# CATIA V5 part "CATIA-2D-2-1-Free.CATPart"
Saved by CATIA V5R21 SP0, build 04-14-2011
Part number: CATIA-2D-2-1-Free
Bounding box of the stored display mesh (mm): x -1249.99 to 1249.99, y 0 to 0, z -1200.054 to 1124.626
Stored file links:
  C:\Users\Rasoul Mohammadi\Desktop\CATIA-Free\2D\CATIA-2D-2-1-Free.CATPart
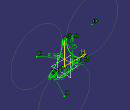
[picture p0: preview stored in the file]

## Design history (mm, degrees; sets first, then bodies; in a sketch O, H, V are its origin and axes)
Body1 (main body)
  Sketch1 on zx-plane, origin (0, 0, 0), H (-1, 0, 0), V (0, 0, 1)
    arc A1 centre (0, 0) radius 200 from (-197.1935, -33.3875) to (197.1935, -33.3875) ccw
    arc A2 centre (303, -25) radius 50 from (279.6923, -69.2352) to (329.6923, 17.2791) ccw
    point P1 (303, -25)
    arc A3 centre (0, -600.0574) radius 600 from (197.1935, -33.3875) to (279.6923, -69.2352) cw
    point P3 (197.1935, -33.3875)
    point P4 (279.6923, -69.2352)
    point P6 (-197.1935, -33.3875)
    point P7 (-279.6923, -69.2352)
    arc A4 centre (-303, -25) radius 50 from (-279.6923, -69.2352) to (-329.6923, 17.2791) cw
    arc A5 centre (0, -600.0574) radius 600 from (-197.1935, -33.3875) to (-279.6923, -69.2352) ccw
    arc A6 centre (0, 525) radius 50 from (50, 524.9714) to (-50, 524.9714) ccw
    point P9 (0, 525)
    arc A7 centre (649.9999, 524.6281) radius 600 from (329.6923, 17.2791) to (50, 524.9714) cw
    point P11 (329.6923, 17.2791)
    point P12 (50, 524.9714)
    point P13 (-50, 524.9714)
    point P14 (-329.6923, 17.2791)
    arc A8 centre (-649.9999, 524.6281) radius 600 from (-329.6923, 17.2791) to (-50, 524.9714) ccw
    point P16 (279.6923, -69.2352)
    point P17 (-279.6923, -69.2352)
    point P18 (-50, 524.9714)
    point P19 (50, 524.9714)
    distance H P9 = 525
    distance H P1 = 25
    distance V P1 = 303
    radius A5 = 600
    radius A4 = 50
    radius A6 = 50
    radius A8 = 600
    radius A1 = 200
    coincidence: P4 A2, P9 V, P12 A6, A3 P16, A5 P17, A8 P18, A7 P19
    symmetry: P3 P6 V, P4 P7 V, A2 A4 V, A3 A5 V, P12 P13 V, P11 P14 V, A7 A8 V
    tangency: A2 A3, A7 A2, A6 A8
    concentricity: A5 A3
